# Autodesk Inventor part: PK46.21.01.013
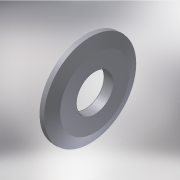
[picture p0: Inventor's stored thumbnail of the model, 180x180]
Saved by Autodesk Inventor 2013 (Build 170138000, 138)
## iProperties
Created: 2005-04
Part Number: PK46.21.01.013
Material: Steel, Mild
Document SubType Name: Modeling
Designer: salex
Manufacturer: Standard
Standards Organization: Custom
Density: 7.86 g/cm^3
Author: salex
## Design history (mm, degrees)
sketch "Эскиз1"
  geometry: L1 (0, 0)-(60.273, 0); L2 (0, 100)-(0, 40); L3 (0, 40)-(20, 40); L4 (20, 40)-(20, 75); L5 (20, 75)-(10, 100); L6 (10, 100)-(0, 100)
  constraints: 12 end point, 2 parallel, 2 perpendicular, 1 horizontal, 1 other
  dimensions: "d0" = 0 distance from line of L1.start L2; "d1" = 20 distance of L2.end L3.end; "d2" = 10 distance of L5.end L2.start; "d3" = 80 diameter of L3 L1; "d4" = 200 diameter of L6 L1; "d5" = 150 diameter of L4.end L1
revolve "Вращение1" sketch "Эскиз1" stored, may be unused: angle "d6" = 90 deg
body "Solid1"
